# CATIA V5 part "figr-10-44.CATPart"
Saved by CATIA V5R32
Part number: Part1
Bounding box of the stored display mesh (mm): x -20 to 20, y -0.339 to 152.641, z -44.55 to 10.195
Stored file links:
  D:\PROJECTS\Project 2022\CATIA V5 6R 2022\Resources\Part Files\c10_catia_v5_6r2022_prt\c10_catia_v5_6r2022_prt\figr-10-44.CATPart
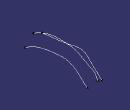
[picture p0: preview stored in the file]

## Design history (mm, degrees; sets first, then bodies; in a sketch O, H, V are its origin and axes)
Set1
  Plane1: type Offset, RefPlane yz-plane, Offset 20, reversed
  Sketch1 on yz-plane, origin (0, 0, 0), H (0, 1, 0), V (0, 0, 1)
    spline S1 through (-0.3393, -8.9363) (20.4957, 1.6782) (43.9804, 9.0119) (85.9797, 8.8277) (110.0875, 1.9736) (113.4186, 0.0053) (148.283, -20.6228) (152.6411, -30.7916)
  Sketch2 on Plane1, origin (-20, 0, 0), H (0, 1, 0), V (0, 0, 1)
    spline S1 through (0, -18.2863) (39.7074, -13.5111) (76.5446, -6.6894) (104.5136, -9.077) (112.3585, -15.8987) (129.7538, -32.6118) (143.3972, -44.5498)
  Plane2: type Offset, RefPlane yz-plane, Offset 20
  Sketch3 on Plane2, origin (20, 0, 0), H (0, 1, 0), V (0, 0, 1)
    spline S1 through (0, -29.0463) (25.3574, -14.3797) (67.652, -5.1704) (115.4039, -10.2866) (140.3031, -31.4339) (148.4891, -38.2556)
Body1 (main body)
